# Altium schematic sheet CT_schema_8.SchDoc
size 297 x 239 mm
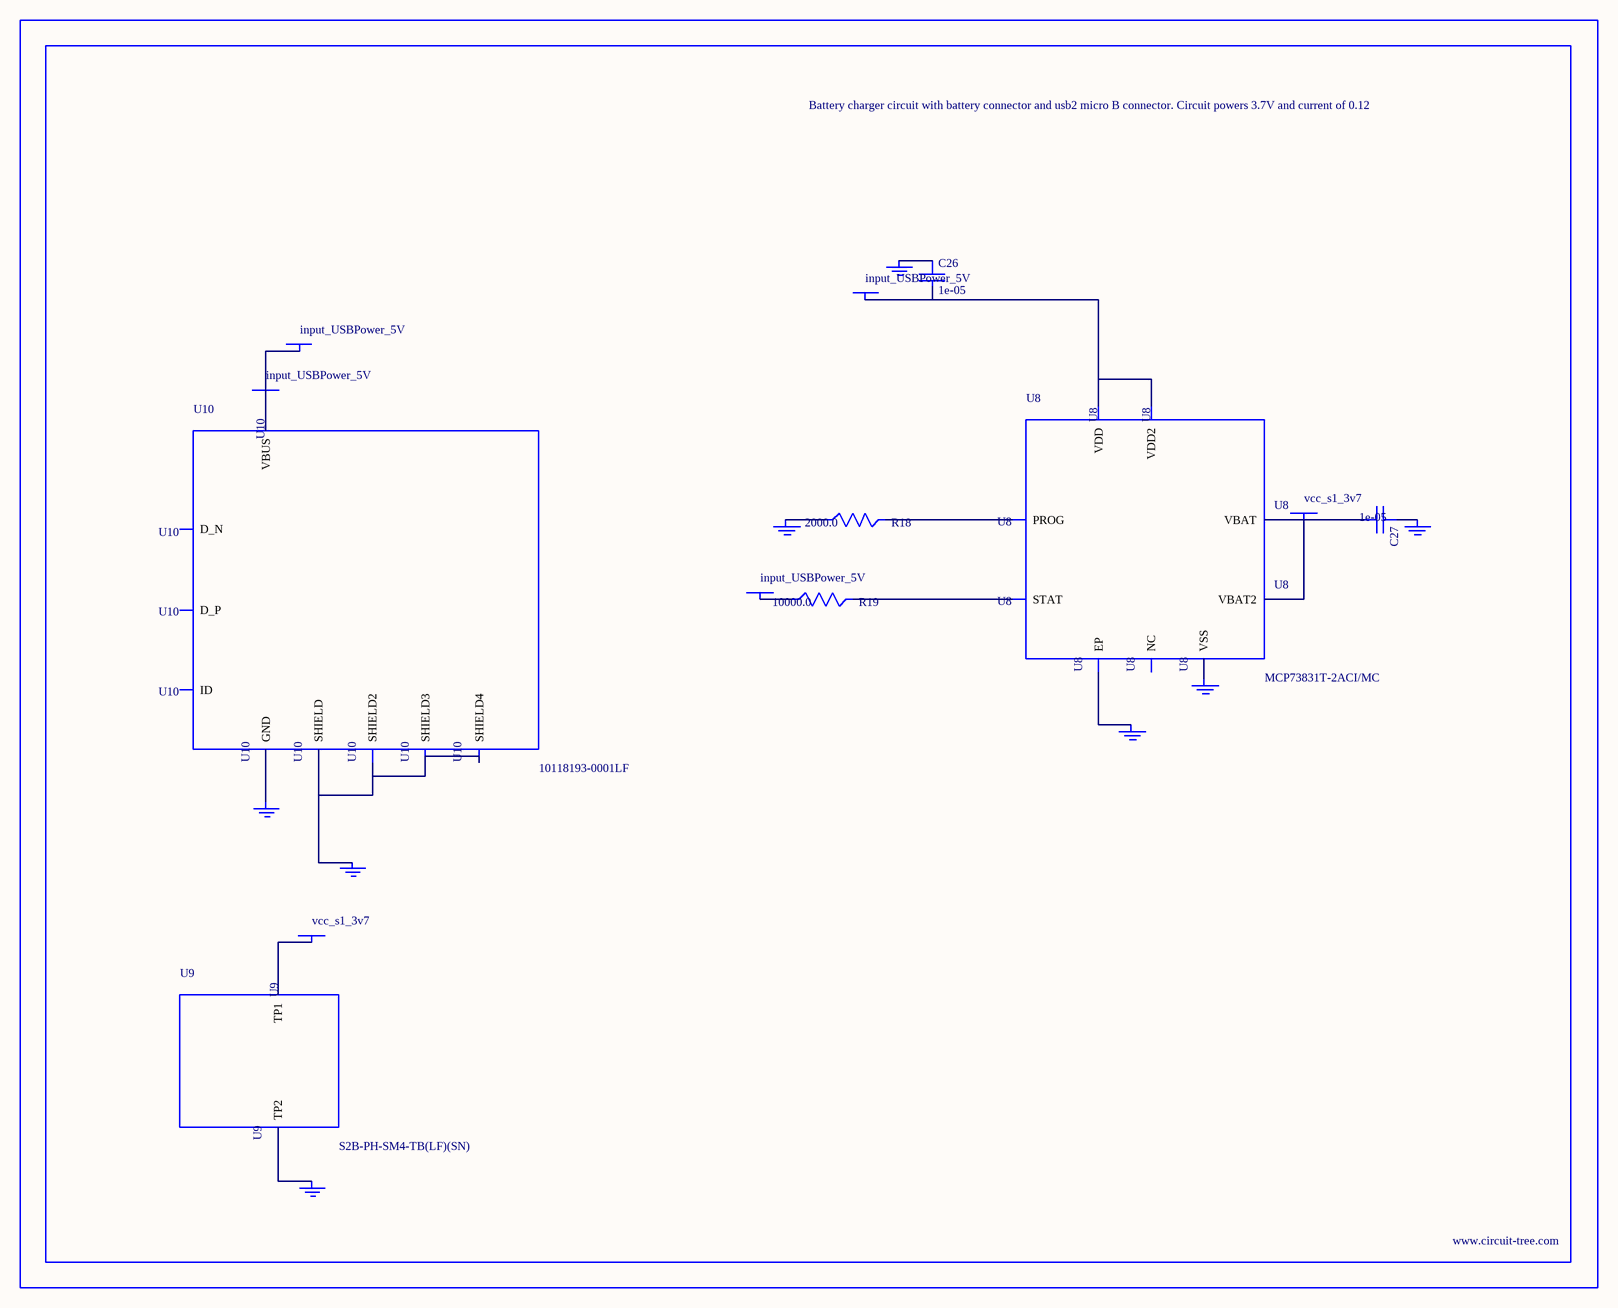
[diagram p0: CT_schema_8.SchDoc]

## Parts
BORDER7  (no value)
C26  1e-05  [C1206]
C27  1e-05  [C1206]
GND_INSTANCE_7_0  (no value)
GND_INSTANCE_7_1  (no value)
GND_INSTANCE_7_2  (no value)
GND_INSTANCE_7_3  (no value)
GND_INSTANCE_7_4  (no value)
GND_INSTANCE_7_5  (no value)
GND_INSTANCE_7_6  (no value)
GND_INSTANCE_7_7  (no value)
POWER_INSTANCE_7_0  input_USBPower_5V
POWER_INSTANCE_7_1  input_USBPower_5V
POWER_INSTANCE_7_2  vcc_s1_3v7
POWER_INSTANCE_7_3  vcc_s1_3v7
POWER_INSTANCE_7_4  input_USBPower_5V
POWER_INSTANCE_7_5  input_USBPower_5V
R18  2000.0  [R0603]
R19  10000.0  [R0603]
U8  MCP73831T-2ACI/MC  [DFN8_2X3MC]
U9  S2B-PH-SM4-TB(LF)(SN)  [JST-2-SMD]
U10  10118193-0001LF  [FCI_10118193-0001LF]

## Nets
NetC26_1: C26.1 GND_INSTANCE_7_0.0(GND)
NetC26_2: C26.2 POWER_INSTANCE_7_0.0(PWR) U8.1(VDD) U8.2(VDD2)
NetC27_1: C27.1 GND_INSTANCE_7_1.0(GND)
NetC27_2: C27.2 POWER_INSTANCE_7_2.0(PWR) U8.3(VBAT) U8.4(VBAT2)
NetGND_INSTANCE_7_2_0: GND_INSTANCE_7_2.0(GND) R18.1
NetGND_INSTANCE_7_3_0: GND_INSTANCE_7_3.0(GND) U8.9(EP)
NetGND_INSTANCE_7_4_0: GND_INSTANCE_7_4.0(GND) U8.6(VSS)
NetGND_INSTANCE_7_5_0: GND_INSTANCE_7_5.0(GND) U9.2(TP2)
NetGND_INSTANCE_7_6_0: GND_INSTANCE_7_6.0(GND) U10.6(SHIELD) U10.7(SHIELD2) U10.8(SHIELD3) U10.9(SHIELD4)
NetGND_INSTANCE_7_7_0: GND_INSTANCE_7_7.0(GND) U10.5(GND)
NetPOWER_INSTANCE_7_1_0: POWER_INSTANCE_7_1.0(PWR) R19.1
NetPOWER_INSTANCE_7_3_0: POWER_INSTANCE_7_3.0(PWR) U9.1(TP1)
NetPOWER_INSTANCE_7_4_0: POWER_INSTANCE_7_4.0(PWR) POWER_INSTANCE_7_5.0(PWR) U10.1(VBUS)
NetR18_2: R18.2 U8.8(PROG)
NetR19_2: R19.2 U8.5(STAT)

Not connected (* = marked no-connect by the designer): U8 7(NC); U10 2(D_N) 3(D_P) 4(ID)

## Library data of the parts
BORDER7 = BORDER_PAGE7
C26 C27 = C1206C106K3RACTU
GND_INSTANCE_7_0-GND_INSTANCE_7_7 = GND
POWER_INSTANCE_7_0-POWER_INSTANCE_7_5 = PWR
R18 = RC0603JR-072KL
R19 = RC0603JR-0710KL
